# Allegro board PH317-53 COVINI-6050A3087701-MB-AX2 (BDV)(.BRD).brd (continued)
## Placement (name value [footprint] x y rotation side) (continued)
C4146  1uF_6.3V_2  [CSC_100X050X055_2]  124.96 61.7 270 top
C4147  1uF_6.3V_2  [CSC_100X050X055_2]  112.47 62.28 180 top
C4148  10uF_6.3V_3  [CSC_160X080X095_2]  115.41 69.45 0 top
C4149  10uF_6.3V_3  [CSC_160X080X095_2]  115.08 66.09 90 top
C4150  1uF_6.3V_2  [CSC_100X050X055_2]  114.22 63.35 90 top
C4151  1uF_6.3V_2  [CSC_100X050X055_2]  120.27 63.17 90 top
C4152  10uF_6.3V_3  [CSC_160X080X095_2]  121.43 65.1 0 top
C4153  10uF_6.3V_3  [CSC_160X080X095_2]  127 65.51 180 top
C4154  1uF_6.3V_2  [CSC_100X050X055_2]  123.9 72.27 90 top
C4155  1uF_6.3V_2  [CSC_100X050X055_2]  112.16 69.73 270 top
C4156  10uF_6.3V_3  [CSC_160X080X095_2]  123.64 65.76 90 top
C4157  1uF_6.3V_2  [CSC_100X050X055_2]  117.24 70.16 90 top
C4165  0.1uF_16V_2  [CSC_100X050X040_2]  86.51 123.42 90 top
C4167  0.1uF_16V_2  [CSC_100X050X040_2]  82.93 125.35 270 top
C4169  0.022uF_16V_2  [CSC_100X050X040_2]  83.46 126.62 180 top
C4170  0.1uF_16V_2  [CSC_100X050X040_2]  127.12 62.06 0 top
C4171  0.1uF_16V_2  [CSC_100X050X040_2]  79.68 123.55 180 top
C4172  0.022uF_16V_2  [CSC_100X050X040_2]  81.3 122.66 180 top
C4300  220pF_50V_2  [CSC_100X050X040_2]  275.99 75.21 180 top
C4301  CSC0402_DY  [CSC_100X050X040_2]  60.93 58.04 270 bottom
C4303  4.7uF_6.3V_3  [CSC_160X080X080_2]  70.23 57.61 0 bottom
C4304  0.1uF_16V_2  [CSC_100X050X040_2]  70.48 58.75 0 bottom
C4305  220pF_50V_2  [CSC_100X050X040_2]  60.93 56.42 90 bottom
C4306  CSC0402_DY  [CSC_100X050X040_2]  273.94 75.21 0 top
C4307  4.7uF_6.3V_3  [CSC_160X080X080_2]  280.51 70.59 0 bottom
C4308  0.1uF_16V_2  [CSC_100X050X040_2]  280.59 71.99 0 bottom
C4450  0.1uF_16V_2  [CSC_100X050X040_2]  147.85 112.73 270 bottom
C4451  1000PF_50V_2  [CSC_100X050X055_2]  146.22 112.58 180 bottom
C4500  47UF_6.3V_5  [CSC_200X125X145_2]  111.96 147.93 0 bottom
C4501  47UF_6.3V_5  [CSC_200X125X145_2]  118.46 147.96 180 bottom
C4502  47UF_6.3V_5  [CSC_200X125X145_2]  132.25 147.93 0 bottom
C4503  47UF_6.3V_5  [CSC_200X125X145_2]  100.2 156.14 180 top
C4508  10uF_6.3V_2  [CSC_100X050X070_2]  121.26 125.53 180 top
C4509  22uF_6.3V_3  [CSC_160X080X100_2]  102.99 134.01 180 top
C4510  22uF_6.3V_3  [CSC_160X080X100_2]  102.99 135.23 180 top
C4511  22uF_6.3V_3  [CSC_160X080X100_2]  102.99 131.58 180 top
C4512  22uF_6.3V_3  [CSC_160X080X100_2]  102.99 132.79 180 top
C4513  22uF_6.3V_3  [CSC_160X080X100_2]  109.01 133.15 180 top
C4514  22uF_6.3V_3  [CSC_160X080X100_2]  109.01 131.93 180 top
C4515  22uF_6.3V_3  [CSC_160X080X100_2]  113.15 131.98 0 top
C4516  10uF_6.3V_2  [CSC_100X050X070_2]  117.9 136.63 0 top
C4517  10uF_6.3V_2  [CSC_100X050X070_2]  117.9 135.74 0 top
C4518  10uF_6.3V_2  [CSC_100X050X070_2]  103.25 129.95 180 top
C4519  10uF_6.3V_2  [CSC_100X050X070_2]  103.22 128.98 180 top
C4520  10uF_6.3V_2  [CSC_100X050X070_2]  115.67 135.72 0 top
C4521  10uF_6.3V_2  [CSC_100X050X070_2]  115.67 136.61 0 top
C4522  10uF_6.3V_2  [CSC_100X050X070_2]  105.18 128.94 270 top
C4523  10uF_6.3V_2  [CSC_100X050X070_2]  109.29 128.94 270 top
C4524  10uF_6.3V_2  [CSC_100X050X070_2]  112.27 128.94 270 top
C4525  10uF_6.3V_2  [CSC_100X050X070_2]  115.67 134.83 0 top
C4526  10uF_6.3V_2  [CSC_100X050X070_2]  110.18 128.94 270 top
C4527  10uF_6.3V_2  [CSC_100X050X070_2]  111.38 128.94 270 top
C4528  10uF_6.3V_2  [CSC_100X050X070_2]  105.41 136.05 180 top
C4529  10uF_6.3V_2  [CSC_100X050X070_2]  103.48 138.57 270 top
C4530  10uF_6.3V_2  [CSC_100X050X070_2]  119.76 128.94 270 top
C4531  10uF_6.3V_2  [CSC_100X050X070_2]  116.2 128.94 270 top
C4532  10uF_6.3V_2  [CSC_100X050X070_2]  105.41 136.94 180 top
C4533  10uF_6.3V_2  [CSC_100X050X070_2]  106.7 128.93 270 top
C4534  10uF_6.3V_2  [CSC_100X050X070_2]  117.9 134.85 0 top
C4535  10uF_6.3V_2  [CSC_100X050X070_2]  114.58 128.93 270 top
C4536  10uF_6.3V_2  [CSC_100X050X070_2]  117.98 128.94 270 top
C4537  10uF_6.3V_2  [CSC_100X050X070_2]  117.09 128.94 270 top
C4538  22uF_6.3V_3  [CSC_160X080X100_2]  113.15 133.2 0 top
C4539  22uF_6.3V_3  [CSC_160X080X100_2]  109.01 135.59 180 top
C4540  22uF_6.3V_3  [CSC_160X080X100_2]  131.11 138.81 0 top
C4541  22uF_6.3V_3  [CSC_160X080X100_2]  131.11 137.6 0 top
C4549  1uF_6.3V_2  [CSC_100X050X055_2]  114.58 127.23 180 top
C4551  22uF_6.3V_3  [CSC_160X080X100_2]  113.15 135.67 0 top
C4552  1uF_6.3V_2  [CSC_100X050X055_2]  117.96 126.85 90 top
C4554  22uF_6.3V_3  [CSC_160X080X080_2]  100.66 134.01 0 top
C4555  22uF_6.3V_3  [CSC_160X080X100_2]  94.03 130.1 180 top
C4556  1uF_6.3V_2  [CSC_100X050X055_2]  109.42 126.85 90 top
C4557  1uF_6.3V_2  [CSC_100X050X055_2]  110.31 126.85 90 top
C4558  1uF_6.3V_2  [CSC_100X050X055_2]  111.43 126.85 90 top
C4559  1uF_6.3V_2  [CSC_100X050X055_2]  115.97 138.57 270 top
C4560  1uF_6.3V_2  [CSC_100X050X055_2]  117.07 126.85 90 top
C4561  1uF_6.3V_2  [CSC_100X050X055_2]  116.18 126.85 90 top
C4562  1uF_6.3V_2  [CSC_100X050X055_2]  119.81 126.85 90 top
C4563  1uF_6.3V_2  [CSC_100X050X055_2]  111.3 138.57 270 top
C4566  1uF_6.3V_2  [CSC_100X050X055_2]  118.29 138.57 270 top
C4568  1uF_6.3V_2  [CSC_100X050X055_2]  103.38 126.85 90 top
C4580  22uF_6.3V_3  [CSC_160X080X100_2]  100.66 132.79 0 top
C4581  22uF_6.3V_3  [CSC_160X080X100_2]  94.03 133.76 180 top
C4582  22uF_6.3V_3  [CSC_160X080X100_2]  94.03 132.54 180 top
C4583  22uF_6.3V_3  [CSC_160X080X100_2]  94.03 131.32 180 top
C4584  22uF_6.3V_3  [CSC_160X080X100_2]  100.66 130.36 0 top
C4585  22uF_6.3V_3  [CSC_160X080X100_2]  100.66 131.58 0 top
C4588  22uF_6.3V_3  [CSC_160X080X080_2]  100.66 135.23 0 top
C4589  47UF_6.3V_5  [CSC_200X125X145_2]  85.06 150.4 90 bottom
C4594  12pF_50V_2  [CSC_100X050X040_2]  136.7 121.69 270 bottom
C4598  22uF_6.3V_3  [CSC_160X080X100_2]  113.15 134.45 0 top
C4599  22uF_6.3V_3  [CSC_160X080X100_2]  109.01 134.37 180 top
C4600  47UF_6.3V_5  [CSC_200X125X145_2]  86.74 150.4 90 bottom
C4602  47UF_4V_3  [CSC_160X080X100_2]  94.03 134.98 180 top
C4612  47pF_50V_2  [CSC_100X050X040_2]  86.53 140.51 0 top
C4614  1uF_6.3V_2  [CSC_100X050X055_2]  106.6 126.83 90 top
C4626  0.01uF_50V_2  [CSC_100X050X040_2]  71.45 95.41 180 bottom
C4627  1uF_6.3V_2  [CSC_100X050X055_2]  97.84 125.84 180 top
C4628  1uF_6.3V_2  [CSC_100X050X055_2]  90.68 130.05 270 top
C4629  1uF_6.3V_2  [CSC_100X050X055_2]  87.17 130.16 90 top
C4630  1uF_6.3V_2  [CSC_100X050X055_2]  92.53 126.41 180 top
C4631  1uF_6.3V_2  [CSC_100X050X055_2]  92.27 127.3 180 top
C4656  10uF_6.3V_2  [CSC_100X050X070_2]  90.27 132.26 180 top
C4657  10uF_6.3V_2  [CSC_100X050X070_2]  100.53 126.47 0 top
C4658  10uF_6.3V_2  [CSC_100X050X070_2]  97.69 138.89 270 top
C4659  10uF_6.3V_2  [CSC_100X050X070_2]  94.03 129.04 180 top
C4660  1uF_6.3V_2  [CSC_100X050X055_2]  90.75 135.01 180 top
C4661  1uF_6.3V_2  [CSC_100X050X055_2]  98.17 127.18 180 top
C4662  1uF_6.3V_2  [CSC_100X050X055_2]  100.63 129.29 0 top
C4663  1uF_6.3V_2  [CSC_100X050X055_2]  87.45 126.72 180 top
C4667  1uF_6.3V_2  [CSC_100X050X055_2]  105 126.83 90 top
C4668  1uF_6.3V_2  [CSC_100X050X055_2]  93.77 137.29 180 top
C4669  1uF_6.3V_2_DY  [CSC_100X050X055_2]  117.9 132.19 0 top
C4670  1uF_6.3V_2_DY  [CSC_100X050X055_2]  117.9 131.3 0 top
C4679  10uF_6.3V_2_DY  [CSC_100X050X070_2]  107.49 126.83 90 top
C4680  10uF_6.3V_2  [CSC_100X050X070_2]  90.63 133.53 270 top
C4681  10uF_6.3V_2  [CSC_100X050X070_2]  100.84 138.84 270 top
C4682  10uF_6.3V_2  [CSC_100X050X070_2]  88.85 128.61 180 top
C4683  10uF_6.3V_2  [CSC_100X050X070_2]  99.57 138.84 270 top
C4684  10uF_6.3V_2_DY  [CSC_100X050X070_2]  106.47 133.38 0 top
C4685  10uF_6.3V_2_DY  [CSC_100X050X070_2]  117.9 133.07 0 top
C4686  10uF_6.3V_2_DY  [CSC_100X050X070_2]  105.84 138.59 270 top
C4687  10uF_6.3V_2  [CSC_100X050X070_2]  94.89 127.16 180 top
C4688  10uF_6.3V_2  [CSC_100X050X070_2]  94 136.05 180 top
C4689  10uF_6.3V_2_DY  [CSC_100X050X070_2]  120.09 134.62 0 top
C4690  10uF_6.3V_2_DY  [CSC_100X050X070_2]  106.47 131.6 0 top
C4691  10uF_6.3V_2_DY  [CSC_100X050X070_2]  106.47 132.49 0 top
C4692  10uF_6.3V_2_DY  [CSC_100X050X070_2]  109.24 136.66 180 top
C4693  10uF_6.3V_2_DY  [CSC_100X050X070_2]  106.47 134.27 0 top
C4694  10uF_6.3V_2_DY  [CSC_100X050X070_2]  113.1 136.73 0 top
C4695  10uF_6.3V_2_DY  [CSC_100X050X070_2]  113.69 128.93 270 top
C4696  10uF_6.3V_2_DY  [CSC_100X050X070_2]  107.59 128.93 270 top
C4697  1uF_6.3V_2  [CSC_100X050X055_2]  117.4 138.57 270 top
C4698  10uF_6.3V_2_DY  [CSC_100X050X070_2]  114.22 130.92 0 top
C4699  1uF_6.3V_2  [CSC_100X050X055_2]  108.15 138.57 270 top
C4700  10uF_6.3V_2  [CSC_100X050X070_2]  112.8 125.56 90 top
C4701  10uF_6.3V_2  [CSC_100X050X070_2]  113.69 125.56 90 top
C4702  CSC0201_DY  [CSC_060X030X030_2]  64.28 70.95 270 bottom
C4703  47UF_6.3V_5  [CSC_200X125X145_2]  136.65 160.99 90 top
C4704  CSC0201_DY  [CSC_060X030X030_2]  83.74 139.07 270 top
C4705  CSC0201_DY  [CSC_060X030X030_2]  251.13 46.26 0 top
C4706  47UF_6.3V_5  [CSC_200X125X145_2]  138.33 160.99 90 top
C4707  CSC0201_DY  [CSC_060X030X030_2]  247.93 34.47 270 bottom
C4708  22uF_6.3V_3  [CSC_160X080X100_2]  139.8 161.24 90 top
C4709  22uF_6.3V_3  [CSC_160X080X100_2]  141.14 161.24 90 top
C4710  10uF_6.3V_2_DY  [CSC_100X050X070_2]  105.41 135.16 180 top
C4711  10uF_6.3V_2_DY  [CSC_100X050X070_2]  117.9 133.96 0 top
C4712  1uF_6.3V_2  [CSC_100X050X055_2]  244.01 33.07 270 bottom
C4713  1uF_6.3V_2  [CSC_100X050X055_2]  247.44 33.05 0 bottom
C4714  1uF_6.3V_2  [CSC_100X050X055_2]  243.35 31.25 270 bottom
C4715  10uF_6.3V_2_DY  [CSC_100X050X070_2]  115.92 133.94 0 top
C4716  22uF_6.3V_3  [CSC_160X080X100_2]  133.47 141.96 0 top
C4717  10uF_6.3V_3  [CSC_160X080X095_2]  133.47 139.53 0 top
C4718  22uF_6.3V_3  [CSC_160X080X100_2]  133.47 140.74 0 top
C4719  22uF_6.3V_3  [CSC_160X080X100_2]  133.47 143.18 0 top
C4720  47UF_6.3V_5  [CSC_200X125X145_2]  113.94 156.09 0 top
C4721  47UF_6.3V_5_DY  [CSC_200X125X145_2]  116.28 157.74 180 top
C4722  47UF_6.3V_5_DY  [CSC_200X125X145_2]  101.32 157.81 180 top
C4723  47UF_6.3V_5_DY  [CSC_200X125X145_2]  116.89 156.09 180 top
C4726  1uF_6.3V_2  [CSC_100X050X055_2]  90.99 125.94 90 top
C4729  1uF_6.3V_2  [CSC_100X050X055_2]  126.46 136.83 270 top
C4730  1uF_6.3V_2  [CSC_100X050X055_2]  122.6 137.16 270 top
C4731  10uF_6.3V_2  [CSC_100X050X070_2]  122.73 129.49 270 top
C4732  22uF_6.3V_3  [CSC_160X080X100_2]  123.14 109.02 0 top
C4733  10uF_6.3V_2  [CSC_100X050X070_2]  122.65 131.91 90 top
C4744  1uF_6.3V_2  [CSC_100X050X055_2]  102.49 126.85 90 top
C4745  1uF_6.3V_2  [CSC_100X050X055_2]  107.26 138.57 270 top
C4746  1uF_6.3V_2  [CSC_100X050X055_2]  102.59 138.57 270 top
C4753  1uF_6.3V_2  [CSC_100X050X055_2]  104.95 138.59 270 top
C4758  1uF_6.3V_2  [CSC_100X050X055_2]  112.65 138.57 270 top
C4760  1uF_6.3V_2  [CSC_100X050X055_2]  96.72 137.06 0 top
C4761  1uF_6.3V_2  [CSC_100X050X055_2]  99.01 137.06 0 top
C4763  10uF_6.3V_2  [CSC_100X050X070_2]  104.52 124.74 90 top
C4764  22uF_6.3V_3  [CSC_160X080X100_2]  123.14 107.8 0 top
C4765  22uF_6.3V_3  [CSC_160X080X100_2]  86.08 107.34 180 top
C4766  1uF_6.3V_2  [CSC_100X050X055_2]  121.26 138.33 90 top
C4767  18pF_50V_2  [CSC_100X050X040_2]  263.43 38.13 180 bottom
C4768  10uF_6.3V_2  [CSC_100X050X070_2]  98.19 124.95 180 top
C4769  10uF_6.3V_2  [CSC_100X050X070_2]  98.24 123.45 180 top
C4770  10uF_6.3V_2  [CSC_100X050X070_2]  110.26 124.16 270 top
C4771  10uF_6.3V_2  [CSC_100X050X070_2]  85.72 108.41 180 top
C4772  10uF_6.3V_2  [CSC_100X050X070_2]  100.94 125.23 90 top
C4773  10uF_6.3V_2  [CSC_100X050X070_2]  122.88 124.87 0 top
C4774  10uF_6.3V_2  [CSC_100X050X070_2]  85.72 109.3 180 top
C4775  10uF_6.3V_2  [CSC_100X050X070_2]  88.82 125.48 180 top
C4776  22uF_6.3V_3  [CSC_160X080X100_2]  85.72 121.82 180 top
C4778  10uF_6.3V_2  [CSC_100X050X070_2]  119.33 141.58 180 top
C4779  10uF_6.3V_2  [CSC_100X050X070_2]  119.33 140.69 180 top
C4780  10uF_6.3V_2  [CSC_100X050X070_2]  123.77 141.53 270 top
C4781  10uF_6.3V_2  [CSC_100X050X070_2]  119.48 138.45 270 top
C4782  10uF_6.3V_2  [CSC_100X050X070_2]  122.88 141.53 270 top
C4783  10uF_6.3V_2  [CSC_100X050X070_2]  120.57 135.87 270 top
C4785  1uF_6.3V_2  [CSC_100X050X055_2]  87.67 138.64 180 top
C4786  1uF_6.3V_2  [CSC_100X050X055_2]  90.1 125.94 90 top
C4787  10uF_6.3V_2  [CSC_100X050X070_2]  121.59 139.93 0 top
C4788  18pF_50V_2  [CSC_100X050X040_2]  261.8 38.13 0 bottom
C4789  1uF_6.3V_2  [CSC_100X050X055_2]  120.37 138.45 270 top
C4790  1uF_6.3V_2  [CSC_100X050X055_2]  122.68 143.34 0 top
C4791  1uF_6.3V_2  [CSC_100X050X055_2]  142.24 160.91 90 top
C4797  1uF_6.3V_2  [CSC_100X050X055_2]  90.45 128.78 0 top
C4800  1uF_6.3V_2  [CSC_100X050X055_2]  113.54 138.57 270 top
C4802  0.1uF_16V_2_DY  [CSC_100X050X040_2]  111.58 59.08 90 bottom
C4807  1uF_6.3V_2  [CSC_100X050X055_2]  115.09 138.57 270 top
C4808  1uF_6.3V_2  [CSC_100X050X055_2]  110.41 138.57 270 top
C4809  22uF_6.3V_3  [CSC_160X080X100_2]  241.68 71.71 180 bottom
C4810  0.22uF_6.3V_1  [CSC_060X030X030_2]  135.35 130.76 180 bottom
C4811  0.22uF_6.3V_1  [CSC_060X030X030_2]  135.35 130.15 180 bottom
C4812  0.22uF_6.3V_1  [CSC_060X030X030_2]  134.95 132.03 180 bottom
C4813  1uF_6.3V_2  [CSC_100X050X055_2]  258.44 61.6 0 top
C4814  0.1uF_16V_2  [CSC_100X050X040_2]  263.67 39.93 0 bottom
C4815  1uF_6.3V_2  [CSC_100X050X055_2]  242.74 55.1 180 top
C4816  1uF_6.3V_2  [CSC_100X050X055_2]  254.43 35.44 0 bottom
C4817  1uF_6.3V_2  [CSC_100X050X055_2]  254.45 46.28 180 top
C4818  0.22uF_6.3V_1  [CSC_060X030X030_2]  134.74 129.54 180 bottom
C4819  0.22uF_6.3V_1  [CSC_060X030X030_2]  133.04 128.07 180 bottom
C4820  0.22uF_6.3V_1  [CSC_060X030X030_2]  134.74 128.93 180 bottom
C4821  0.22uF_6.3V_1  [CSC_060X030X030_2]  138.66 128.98 180 bottom
C4822  0.22uF_6.3V_1  [CSC_060X030X030_2]  133.04 128.68 180 bottom
C4823  0.22uF_6.3V_1  [CSC_060X030X030_2]  138.66 128.38 180 bottom
C4824  1uF_6.3V_2  [CSC_100X050X055_2]  265.25 37.11 0 bottom
C4825  0.1uF_16V_2  [CSC_100X050X040_2]  265.25 38 0 bottom
C4826  15pF_50V_2  [CSC_100X050X040_2]  244.35 70.29 180 bottom
C4827  1uF_6.3V_2  [CSC_100X050X055_2]  259.38 59.97 90 top
C4828  12pF_50V_2  [CSC_100X050X040_2]  247.55 70.29 0 bottom
C4829  1uF_6.3V_2  [CSC_100X050X055_2]  254.1 52.2 270 top
C4830  1uF_6.3V_2  [CSC_100X050X055_2]  254.86 57.92 0 top
C4831  0.22uF_6.3V_1  [CSC_060X030X030_2]  134.95 131.42 180 bottom
C4832  0.22uF_6.3V_1  [CSC_060X030X030_2]  132.41 126.32 180 bottom
C4833  0.22uF_6.3V_1  [CSC_060X030X030_2]  132.41 126.93 180 bottom
C4834  0.22uF_6.3V_1  [CSC_060X030X030_2]  136.7 132.29 180 bottom
C4835  0.22uF_6.3V_1  [CSC_060X030X030_2]  135.28 136.5 180 bottom
C4836  0.22uF_6.3V_1  [CSC_060X030X030_2]  135.28 137.11 180 bottom
C4837  0.22uF_6.3V_1  [CSC_060X030X030_2]  136.7 135.69 180 bottom
C4838  0.22uF_6.3V_1  [CSC_060X030X030_2]  136.7 136.3 180 bottom
C4839  0.22uF_6.3V_1  [CSC_060X030X030_2]  135.28 134.88 180 bottom
C4840  0.22uF_6.3V_1  [CSC_060X030X030_2]  135.28 135.49 180 bottom
C4841  0.22uF_6.3V_1  [CSC_060X030X030_2]  136.7 134.01 180 bottom
C4842  0.22uF_6.3V_1  [CSC_060X030X030_2]  136.7 134.62 180 bottom
C4843  10uF_6.3V_2  [CSC_100X050X070_2]  246.56 57.39 90 top
C4844  1uF_6.3V_2  [CSC_100X050X055_2]  245.67 57.39 90 top
C4845  22uF_6.3V_3  [CSC_160X080X100_2]  241.68 70.49 180 bottom
C4846  1uF_6.3V_2  [CSC_100X050X055_2]  241.68 68.2 180 bottom
C4847  10uF_6.3V_2  [CSC_100X050X070_2]  238.15 67.34 90 top
C4848  1uF_6.3V_2  [CSC_100X050X055_2]  239.49 66.45 0 top
C4849  1uF_6.3V_2  [CSC_100X050X055_2]  239.49 65.56 0 top
C4850  1uF_6.3V_2  [CSC_100X050X055_2]  240.61 54.74 90 top
C4851  10uF_6.3V_2  [CSC_100X050X070_2]  251.02 53.14 0 top
C4852  22uF_6.3V_3  [CSC_160X080X100_2]  231.09 48.87 270 bottom
C4853  1uF_6.3V_2  [CSC_100X050X055_2]  248.13 49.53 270 top
C4854  1uF_6.3V_2  [CSC_100X050X055_2]  244.34 57.23 90 top
C4855  10uF_6.3V_2  [CSC_100X050X070_2]  241.5 54.74 90 top
C4856  10uF_6.3V_2  [CSC_100X050X070_2]  238.45 37.82 270 bottom
C4857  1uF_6.3V_2  [CSC_100X050X055_2]  233.55 38.15 180 bottom
C4858  1uF_6.3V_2  [CSC_100X050X055_2]  237.26 67.34 90 top
C4859  1uF_6.3V_2  [CSC_100X050X055_2]  265.25 38.89 0 bottom
C4860  1uF_6.3V_2  [CSC_100X050X055_2]  243.96 55.99 180 top
C4861  22uF_6.3V_3  [CSC_160X080X100_2]  229.82 48.87 270 bottom
C4862  1uF_6.3V_2  [CSC_100X050X055_2]  238.78 48.06 270 top
C4863  1uF_6.3V_2  [CSC_100X050X055_2]  237.89 48.06 270 top
C4864  1uF_6.3V_2  [CSC_100X050X055_2]  250.64 50.17 270 top
C4865  1uF_6.3V_2  [CSC_100X050X055_2]  247.67 54.64 90 top
C4866  1uF_6.3V_2  [CSC_100X050X055_2]  247.88 57.39 90 top
C4867  0.1uF_16V_2  [CSC_100X050X040_2]  247.24 48.37 90 top
C4868  0.1uF_16V_2  [CSC_100X050X040_2]  249.42 49.43 90 top
C4869  1uF_6.3V_2  [CSC_100X050X055_2]  254.2 54.69 90 top
C4870  1uF_6.3V_2  [CSC_100X050X055_2]  256.26 60.94 270 top
C4871  0.1uF_16V_2  [CSC_100X050X040_2]  252.22 49.81 180 top
C4872  0.1uF_16V_2  [CSC_100X050X040_2]  252.32 52.2 270 top
C4873  22uF_6.3V_3  [CSC_160X080X100_2]  237.36 37.44 270 bottom
C4874  22uF_6.3V_3  [CSC_160X080X100_2]  236.14 37.44 270 bottom
C4875  1uF_6.3V_2  [CSC_100X050X055_2]  261.57 32.06 270 top
C4876  0.1uF_16V_2  [CSC_100X050X040_2]  260.68 32.06 270 top
C4877  22uF_6.3V_3  [CSC_160X080X100_2]  241.5 69.27 180 bottom
C4878  0.22uF_6.3V_1  [CSC_060X030X030_2]  135.94 125.91 180 bottom
C4879  0.22uF_6.3V_1  [CSC_060X030X030_2]  136.7 132.9 180 bottom
C4880  0.22uF_6.3V_1  [CSC_060X030X030_2]  135.94 126.52 180 bottom
C4881  0.22uF_6.3V_1  [CSC_060X030X030_2]  134.67 125.17 180 bottom
C4882  0.22uF_6.3V_1  [CSC_060X030X030_2]  135.25 133.76 180 bottom
C4883  0.22uF_6.3V_1  [CSC_060X030X030_2]  135.25 133.15 180 bottom
C4884  0.22uF_6.3V_1  [CSC_060X030X030_2]  134.67 124.57 180 bottom
C4885  0.22uF_6.3V_1  [CSC_060X030X030_2]  137.31 124.16 180 bottom
C4886  0.22uF_6.3V_1  [CSC_060X030X030_2]  137.31 124.77 180 bottom
C4887  0.22uF_6.3V_1  [CSC_060X030X030_2]  134.67 122.89 180 bottom
C4888  0.22uF_6.3V_1  [CSC_060X030X030_2]  134.67 123.5 180 bottom
C4890  0.1uF_16V_2_DY  [CSC_100X050X040_2]  240.45 53.03 180 top
C4891  0.1uF_16V_2_DY  [CSC_100X050X040_2]  243.46 57.23 90 top
C4892  0.1uF_16V_2_DY  [CSC_100X050X040_2]  240.08 64.67 0 top
C4954  0.01uF_50V_2  [CSC_100X050X040_2]  234.06 41.35 180 bottom
C4955  0.01uF_50V_2  [CSC_100X050X040_2]  234.06 40.47 180 bottom
C4960  0.1uF_16V_2  [CSC_100X050X040_2]  233.73 45.72 0 bottom
C4961  0.1uF_16V_2  [CSC_100X050X040_2]  233.73 44.83 0 bottom
C6035  1000PF_50V_2  [CSC_100X050X055_2]  13.2 77.65 0 bottom
C6036  0.01uF_50V_2  [CSC_100X050X040_2]  11.3 81.46 90 bottom
C6037  1000PF_50V_2  [CSC_100X050X055_2]  15.11 77.02 270 bottom
C6038  0.01uF_50V_2  [CSC_100X050X040_2]  16 77.02 270 bottom
C7000  0.1uF_16V_2  [CSC_100X050X040_2]  75.69 56.09 180 bottom
C7006  0.1uF_25V_2  [CSC_100X050X040_2]  190.22 29.09 180 bottom
C7010  10uF_6.3V_3  [RANGERS-6010B0044902-001]  232.71 31.5 180 bottom
C7011  1000PF_50V_2  [CSC_100X050X055_2]  222.4 27.97 90 bottom
C7012  220pF_50V_2  [CSC_100X050X040_2]  228.19 36.3 90 bottom
C7013  220pF_50V_2  [CSC_100X050X040_2]  229.56 36.3 90 bottom
C7014  1000PF_50V_2  [CSC_100X050X055_2]  279.85 58.9 270 bottom
C7015  100pF_50V_2_DY  [CSC_100X050X040_2]  66.95 74.17 0 bottom
C7016  1uF_6.3V_2  [CSC_100X050X055_2]  277.49 66.02 90 bottom
C7017  1uF_6.3V_2  [CSC_100X050X055_2]  225.07 32.01 180 bottom
C7018  10uF_6.3V_3  [RANGERS-6010B0044902-001]  227.83 37.9 0 bottom
C7019  1uF_6.3V_2  [CSC_100X050X055_2]  229.79 29.11 270 bottom
C7020  1uF_6.3V_2  [CSC_100X050X055_2]  281.25 62.74 270 bottom
C7023  0.1uF_16V_2  [CSC_100X050X040_2]  192.3 31.3 0 bottom
C7032  0.01uF_50V_2  [CSC_100X050X040_2]  230.15 48.31 270 top
C7033  0.22uF_6.3V_2  [CSC_100X050X040_2]  96.34 57.43 0 bottom
C7034  1000PF_50V_2  [CSC_100X050X055_2]  228.14 48.39 270 top
C7035  1000PF_50V_2  [CSC_100X050X055_2]  230.63 57.48 90 top
C7036  0.022uF_16V_2  [CSC_100X050X040_2]  72.01 98.17 270 bottom
C7037  1uF_6.3V_2  [CSC_100X050X055_2]  226.95 52.73 90 top
C7038  1uF_6.3V_2  [CSC_100X050X055_2]  231.34 52.96 90 top
C7039  CSC0402  [CSC_100X050X040_2]  66.85 94.85 90 bottom
C7041  1uF_6.3V_2  [CSC_100X050X055_2]  70.86 92.1 180 bottom
C7042  1uF_6.3V_2  [CSC_100X050X055_2]  73.05 95.41 0 bottom
C7205  10uF_6.3V_3  [RANGERS-6010B0044902-001]  226.64 55.58 180 top
C7500  0.1uF_16V_2  [CSC_100X050X040_2]  170.76 171.38 90 top
C7501  0.1uF_16V_2  [CSC_100X050X040_2]  201.88 150.8 90 top
C7502  0.1uF_16V_2  [CSC_100X050X040_2]  204.54 111.13 90 top
C7503  0.1uF_16V_2  [CSC_100X050X040_2]  180.16 98.05 90 top
C7504  0.1uF_16V_2  [CSC_100X050X040_2]  198.83 81.82 270 bottom
C7505  0.1uF_16V_2  [CSC_100X050X040_2]  158.11 152.15 180 bottom
C7506  0.1uF_16V_2  [CSC_100X050X040_2]  177.92 177.68 180 bottom
C7507  0.1uF_16V_2  [CSC_100X050X040_2]  211.02 133.07 180 bottom
C7508  0.1uF_16V_2  [CSC_100X050X040_2]  186.99 83.65 0 bottom
C7509  0.1uF_16V_2  [CSC_100X050X040_2]  81.89 140.16 0 bottom
C7510  0.1uF_16V_2  [CSC_100X050X040_2]  79.3 129.09 0 bottom
C7511  0.1uF_16V_2  [CSC_100X050X040_2]  83.77 150.4 270 bottom
C7512  0.1uF_16V_2  [CSC_100X050X040_2]  101.32 159.11 0 top
C7513  0.1uF_16V_2  [CSC_100X050X040_2]  113.97 157.38 180 top
C7545  0.1uF_25V_2  [CSC_100X050X040_2]  50.26 39.5 90 bottom
C7546  0.1uF_16V_2  [CSC_100X050X040_2]  137.33 154.44 180 bottom
C7547  0.1uF_16V_2  [CSC_100X050X040_2]  262.51 26.01 0 top
C7548  0.1uF_25V_2  [CSC_100X050X040_2]  65.4 105.85 90 top
C7549  0.1uF_25V_2  [CSC_100X050X040_2]  124.91 34.04 180 top
C7550  0.1uF_16V_2  [CSC_100X050X040_2]  233.22 52.45 90 bottom
C7551  0.1uF_16V_2  [CSC_100X050X040_2]  296.31 81.26 90 top
C7552  0.1uF_16V_2  [CSC_100X050X040_2]  297.61 47.96 0 top
C7553  0.1uF_16V_2  [CSC_100X050X040_2]  308.86 21.42 180 top
C7554  0.1uF_16V_2  [CSC_100X050X040_2]  309.44 20.35 180 top
C7555  0.1uF_16V_2  [CSC_100X050X040_2]  308.86 21.85 180 bottom
C7558  0.1uF_16V_2  [CSC_100X050X040_2]  301.34 135.06 180 bottom
C7559  0.1uF_16V_2  [CSC_100X050X040_2]  301.34 134.17 180 bottom
C7560  0.1uF_25V_2  [CSC_100X050X040_2]  237.94 31.04 0 top
C7561  0.1uF_25V_2  [CSC_100X050X040_2]  44.98 78.79 180 top
C7562  0.1uF_25V_2  [CSC_100X050X040_2]  76.27 156.34 90 top
C7563  0.1uF_25V_2  [CSC_100X050X040_2]  73.76 59.46 0 top
C7564  0.1uF_25V_2  [CSC_100X050X040_2]  194.71 81.31 180 bottom
C7565  0.1uF_25V_2  [CSC_100X050X040_2]  140 47.1 90 top
C7566  0.1uF_25V_2  [CSC_100X050X040_2]  208.18 75.52 0 top
C7567  0.1uF_25V_2  [CSC_100X050X040_2]  168.2 76.51 180 top
C7568  0.1uF_25V_2  [CSC_100X050X040_2]  157.71 154.74 0 bottom
C7569  0.1uF_16V_2  [CSC_100X050X040_2]  301.98 136 180 bottom
C7570  0.1uF_25V_2  [CSC_100X050X040_2]  206.19 29.21 180 top
C7571  0.1uF_25V_2  [CSC_100X050X040_2]  80.21 110.16 270 bottom
C7572  0.1uF_25V_2  [CSC_100X050X040_2]  82.52 71.58 270 bottom
C7573  0.1uF_16V_2  [CSC_100X050X040_2]  300 32.72 270 top
C7574  0.1uF_16V_2  [CSC_100X050X040_2]  301.98 136.88 180 bottom
C7575  0.1uF_16V_2  [CSC_100X050X040_2]  302.13 114.94 180 top
C7576  0.1uF_16V_2  [CSC_100X050X040_2]  302.1 116.51 180 top
C7577  0.1uF_16V_2  [CSC_100X050X040_2]  302.13 114.99 180 bottom
C7578  0.1uF_16V_2  [CSC_100X050X040_2]  302.1 116.34 180 bottom
C7579  0.1uF_16V_2  [CSC_100X050X040_2]  306.73 60.71 0 top
C7580  0.1uF_16V_2  [CSC_100X050X040_2]  306.73 59.41 0 top
C7581  0.1uF_16V_2  [CSC_100X050X040_2]  306.73 59.67 0 bottom
C7582  0.1uF_16V_2  [CSC_100X050X040_2]  306.73 60.66 0 bottom
C7583  0.1uF_16V_2  [CSC_100X050X040_2]  309.44 20.58 180 bottom
C7600  100pF_50V_2  [CSC_100X050X040_2]  24.46 32.97 0 top
C7601  100pF_50V_2  [CSC_100X050X040_2]  28.11 33.94 180 top
C7602  100pF_50V_2  [CSC_100X050X040_2]  26.64 32.01 180 top
C7689  0.1uF_25V_2_DY  [CSC_100X050X040_2]  16.74 32.11 180 top
C7699  0.1uF_25V_2  [CSC_100X050X040_2]  16.74 33 180 top
C50020  0.1uF_16V_2  [CSC_100X050X040_2]  145.84 41.86 0 bottom
C50030  1uF_6.3V_1  [CSC_060X030X039_2]  157.74 134.61 270 top
C50031  1uF_6.3V_1  [CSC_060X030X039_2]  158.34 134.61 270 top
C50032  1uF_6.3V_1  [CSC_060X030X039_2]  156.84 138.54 180 top
C50033  1uF_6.3V_1  [CSC_060X030X039_2]  159.51 139.14 0 top
C50034  1uF_6.3V_1  [CSC_060X030X039_2]  159.53 136.12 0 top
C50035  1uF_6.3V_1  [CSC_060X030X039_2]  156.74 137.27 180 top
C50036  1uF_6.3V_1  [CSC_060X030X039_2]  156.77 136.05 180 top
C50037  1uF_6.3V_1  [CSC_060X030X039_2]  156.77 136.66 180 top
C50038  4.7uF_6.3V_2  [CSC_100X050X065_2]  148.97 166.86 180 top
C50039  4.7uF_6.3V_2  [CSC_100X050X065_2]  156.82 140.08 90 top
C50040  10uF_10V_5  [CSC_200X125X140_2]  151.81 167.96 0 top
C50041  10uF_10V_5  [CSC_200X125X140_2]  151.81 169.62 0 top
C50042  22uF_4V_3  [CSC_160X080X100_2]  151.81 166.37 0 top
C50050  1uF_6.3V_1  [CSC_060X030X039_2]  158.98 140.01 90 top
C50051  1uF_6.3V_1  [CSC_060X030X039_2]  159.51 136.73 0 top
C50052  1uF_6.3V_1  [CSC_060X030X039_2]  159.51 137.33 0 top
C50053  1uF_6.3V_1  [CSC_060X030X039_2]  159.51 137.93 0 top
C50054  1uF_6.3V_1  [CSC_060X030X039_2]  159.51 138.53 0 top
C50055  1uF_6.3V_1  [CSC_060X030X039_2]  156.71 135.13 180 top
C50056  1uF_6.3V_1  [CSC_060X030X039_2]  156.71 134.52 180 top
C50057  1uF_6.3V_1  [CSC_060X030X039_2]  156.74 137.93 180 top
C50058  4.7uF_6.3V_2  [CSC_100X050X065_2]  148.99 165.94 180 top
C50059  10uF_10V_5  [CSC_200X125X140_2]  148.71 169.62 180 top
C50060  22uF_4V_3  [CSC_160X080X100_2]  148.71 167.95 180 top
C50070  1uF_6.3V_1  [CSC_060X030X039_2]  156.83 130.98 180 top
C50071  1uF_6.3V_1  [CSC_060X030X039_2]  159.52 132.07 0 top
C50072  1uF_6.3V_1  [CSC_060X030X039_2]  158.12 130.18 180 top
C50073  1uF_6.3V_1  [CSC_060X030X039_2]  158.12 129.58 180 top
C50074  1uF_6.3V_1  [CSC_060X030X039_2]  156.83 131.58 180 top
C50075  4.7uF_6.3V_2  [CSC_100X050X065_2]  157.04 133.38 180 top
C50076  4.7uF_6.3V_2  [CSC_100X050X065_2]  143.25 139.68 270 bottom
C50077  10uF_10V_5  [CSC_200X125X140_2]  142.63 142.33 90 bottom
C50078  10uF_10V_5  [CSC_200X125X140_2]  141.74 139.06 270 bottom
C50079  22uF_4V_3  [CSC_160X080X100_2]  140.09 139.06 270 bottom
C50080  1uF_6.3V_1  [CSC_060X030X039_2]  156.77 130.23 180 top
C50081  1uF_6.3V_1  [CSC_060X030X039_2]  159.6 129.66 0 top
C50082  1uF_6.3V_1  [CSC_060X030X039_2]  159.6 130.26 0 top
C50083  1uF_6.3V_1  [CSC_060X030X039_2]  159.6 130.86 0 top
C50084  1uF_6.3V_1  [CSC_060X030X039_2]  159.52 131.46 0 top
C50085  4.7uF_6.3V_2  [CSC_100X050X065_2]  145.18 142.35 90 bottom
C50086  10uF_10V_5  [CSC_200X125X140_2]  138.43 139.06 270 bottom
C50087  22uF_4V_3  [CSC_160X080X100_2]  144.07 142.48 90 bottom
C50090  1uF_6.3V_1  [CSC_060X030X039_2]  159.5 132.75 0 top
C50091  1uF_6.3V_1  [CSC_060X030X039_2]  159.51 133.73 0 top
C50092  4.7uF_6.3V_2  [CSC_100X050X065_2]  159.61 134.85 90 top
C50100  1uF_6.3V_1  [CSC_060X030X039_2]  164.26 140.41 270 top
C50101  4.7uF_6.3V_2  [CSC_100X050X065_2]  170.1 140.82 270 top
C50102  4.7uF_6.3V_2  [CSC_100X050X065_2]  179.38 139.2 180 top
C50103  22uF_4V_3  [CSC_160X080X100_2]  188.85 158.55 180 top
C50110  1uF_6.3V_1  [CSC_060X030X039_2]  169.26 141.04 270 top
C50111  1uF_6.3V_1  [CSC_060X030X039_2]  179.15 132.83 180 top
C50200  1uF_6.3V_1  [CSC_060X030X039_2]  179.19 138.43 180 top
C50300  1uF_6.3V_1  [CSC_060X030X039_2]  179.04 123.66 180 top
C50400  1uF_6.3V_1  [CSC_060X030X039_2]  175.03 120.82 90 top
C50510  10uF_4V_3  [CSC_160X080X090_2]  181.68 168.94 180 top
C50511  10uF_4V_3  [CSC_160X080X090_2]  177.2 160.68 270 top
C50512  10uF_4V_3  [CSC_160X080X090_2]  173.21 164.26 270 top
C50513  10uF_4V_3  [CSC_160X080X090_2]  186.99 173.74 90 top
C50514  10uF_4V_3  [CSC_160X080X090_2]  173.07 171.83 90 top
C50515  10uF_4V_3  [CSC_160X080X090_2]  173.07 174.76 90 top
C50516  22uF_4V_3  [CSC_160X080X100_2]  185.24 177.78 180 bottom
C50517  22uF_4V_3  [CSC_160X080X100_2]  182.29 177.78 0 bottom
C50518  22uF_4V_3  [CSC_160X080X100_2]  179.9 177.78 180 bottom
C50519  22uF_4V_3  [CSC_160X080X100_2]  175.89 177.78 0 bottom
C50520  22uF_4V_3  [CSC_160X080X100_2]  189.43 175.31 270 bottom
C50521  22uF_4V_3  [CSC_160X080X100_2]  177.16 175.77 270 top
C50522  1uF_6.3V_1  [CSC_060X030X039_2]  174.27 170.72 90 top
C50523  1uF_6.3V_1  [CSC_060X030X039_2]  185.98 161.9 90 top
C50524  1uF_6.3V_1  [CSC_060X030X039_2]  174.29 174.58 270 top
C50525  1uF_6.3V_1  [CSC_060X030X039_2]  178.23 170.49 270 top
C50526  1uF_6.3V_1  [CSC_060X030X039_2]  176.4 167.21 0 top
C50527  1uF_6.3V_1  [CSC_060X030X039_2]  174.29 163.33 90 top
C50528  1uF_6.3V_1  [CSC_060X030X039_2]  175.23 160.89 0 top
C50529  1uF_6.3V_1  [CSC_060X030X039_2]  174.29 173.08 270 top
C50530  1uF_6.3V_1  [CSC_060X030X039_2]  179.22 173.82 270 top
C50531  1uF_6.3V_1  [CSC_060X030X039_2]  174.32 164.87 90 top
C50532  1uF_6.3V_1  [CSC_060X030X039_2]  174.29 161.8 90 top
C50533  1uF_6.3V_1  [CSC_060X030X039_2]  182.37 170.49 0 top
C50534  1uF_6.3V_1  [CSC_060X030X039_2]  188.49 174.7 270 bottom
C50535  1uF_6.3V_1  [CSC_060X030X039_2]  172.79 171.58 270 bottom
C50536  1uF_6.3V_1  [CSC_060X030X039_2]  185.95 164.8 90 top
C50537  1uF_6.3V_1  [CSC_060X030X039_2]  179.37 163.22 90 top
C50538  1uF_6.3V_1  [CSC_060X030X039_2]  179.38 164.84 90 top
C50539  1uF_6.3V_1  [CSC_060X030X039_2]  185.92 170.87 270 top
C50540  1uF_6.3V_1  [CSC_060X030X039_2]  181.02 174.5 90 top
C50541  1uF_6.3V_1  [CSC_060X030X039_2]  185.95 172.37 90 top
C50542  1uF_6.3V_1  [CSC_060X030X039_2]  181.91 171.96 90 top
C50543  1uF_6.3V_1  [CSC_060X030X039_2]  188.49 173.46 270 bottom
C50544  1uF_6.3V_1  [CSC_060X030X039_2]  174.27 171.83 270 top
C50545  1uF_6.3V_1  [CSC_060X030X039_2]  178.69 171.91 180 top
C50546  4.7uF_6.3V_2  [CSC_100X050X065_2]  182.34 176.28 0 top
C50547  1uF_6.3V_1  [CSC_060X030X039_2]  178.38 161.57 180 top
C50548  1uF_6.3V_1  [CSC_060X030X039_2]  182.04 160.89 0 top
C50549  1uF_6.3V_1  [CSC_060X030X039_2]  178.33 175.52 180 top
C50550  1uF_6.3V_1  [CSC_060X030X039_2]  182.27 175.52 0 top
C50551  1uF_6.3V_1  [CSC_060X030X039_2]  184.3 166.91 180 top
C50552  1uF_6.3V_1  [CSC_060X030X039_2]  181.1 162.56 90 top
C50553  1uF_6.3V_1  [CSC_060X030X039_2]  185.95 163.35 90 top
C50554  1uF_6.3V_1  [CSC_060X030X039_2]  182.39 165.94 0 top
C50555  1uF_6.3V_1  [CSC_060X030X039_2]  185.04 175.52 180 top
C50556  1uF_6.3V_1  [CSC_060X030X039_2]  185.44 168.96 270 top
C50557  1uF_6.3V_1  [CSC_060X030X039_2]  185.98 173.84 90 top
C50558  1uF_6.3V_1  [CSC_060X030X039_2]  185.87 166.6 270 top
C50559  1uF_6.3V_1  [CSC_060X030X039_2]  172.84 174.91 270 bottom
C50560  1uF_6.3V_1  [CSC_060X030X039_2]  174.32 166.37 270 top
C50561  1uF_6.3V_1  [CSC_060X030X039_2]  175.31 175.54 0 top
C50562  1uF_6.3V_1  [CSC_060X030X039_2]  172.82 173.16 270 bottom
C50610  10uF_4V_3  [CSC_160X080X090_2]  156.15 169.47 0 top
C50611  10uF_4V_3  [CSC_160X080X090_2]  164.21 167.82 180 top
C50612  10uF_4V_3  [CSC_160X080X090_2]  157.22 164.65 90 top
C50613  10uF_4V_3  [CSC_160X080X090_2]  156.74 177.78 0 bottom
C50614  10uF_4V_3  [CSC_160X080X090_2]  170.74 174.81 270 top
C50615  10uF_4V_3  [CSC_160X080X090_2]  169.49 162.18 0 top
C50616  22uF_4V_3  [CSC_160X080X100_2]  162.84 177.78 180 bottom
C50617  22uF_4V_3  [CSC_160X080X100_2]  169.44 177.78 180 bottom
C50618  22uF_4V_3  [CSC_160X080X100_2]  161.13 175.75 270 top
C50619  22uF_4V_3  [CSC_160X080X100_2]  172.49 177.78 180 bottom
C50620  22uF_4V_3  [CSC_160X080X100_2]  166.52 177.78 0 bottom
C50621  22uF_4V_3  [CSC_160X080X100_2]  159.15 177.78 0 bottom
C50622  1uF_6.3V_1  [CSC_060X030X039_2]  155.83 174.7 270 bottom
C50623  1uF_6.3V_1  [CSC_060X030X039_2]  155.83 171.63 270 bottom
C50624  1uF_6.3V_1  [CSC_060X030X039_2]  171.57 173.16 270 bottom
C50625  1uF_6.3V_1  [CSC_060X030X039_2]  170.18 173.03 270 top
C50626  1uF_6.3V_1  [CSC_060X030X039_2]  170.1 163.35 90 top
C50627  1uF_6.3V_1  [CSC_060X030X039_2]  157.98 166.75 180 top
C50628  1uF_6.3V_1  [CSC_060X030X039_2]  158.29 174.58 270 top
C50629  1uF_6.3V_1  [CSC_060X030X039_2]  169.41 166.68 0 top
C50630  1uF_6.3V_1  [CSC_060X030X039_2]  155.83 173.18 270 bottom
C50631  1uF_6.3V_1  [CSC_060X030X039_2]  171.57 171.63 270 bottom
C50632  1uF_6.3V_1  [CSC_060X030X039_2]  171.57 174.93 270 bottom
C50633  1uF_6.3V_1  [CSC_060X030X039_2]  161.64 169.7 270 top
C50634  1uF_6.3V_1  [CSC_060X030X039_2]  168.14 167.57 180 top
C50635  1uF_6.3V_1  [CSC_060X030X039_2]  158.26 173.03 270 top
C50636  1uF_6.3V_1  [CSC_060X030X039_2]  161.69 165.97 270 top
C50637  1uF_6.3V_1  [CSC_060X030X039_2]  165.07 164.98 90 top
C50638  1uF_6.3V_1  [CSC_060X030X039_2]  165.07 171.15 90 top
C50639  1uF_6.3V_1  [CSC_060X030X039_2]  165.1 162.72 90 top
C50640  1uF_6.3V_1  [CSC_060X030X039_2]  158.31 165.59 90 top
C50641  1uF_6.3V_1  [CSC_060X030X039_2]  163.27 173.82 270 top
C50642  1uF_6.3V_1  [CSC_060X030X039_2]  170 171.63 270 top
C50643  1uF_6.3V_1  [CSC_060X030X039_2]  168.48 160.83 180 top
C50644  1uF_6.3V_1  [CSC_060X030X039_2]  158.35 164.3 270 top
C50645  1uF_6.3V_1  [CSC_060X030X039_2]  162.43 171.83 90 top
C50646  4.7uF_6.3V_2  [CSC_100X050X065_2]  165.93 176.25 0 top
C50647  1uF_6.3V_1  [CSC_060X030X039_2]  165.1 161.6 90 top
C50648  1uF_6.3V_1  [CSC_060X030X039_2]  162.3 175.54 180 top
C50649  1uF_6.3V_1  [CSC_060X030X039_2]  165.91 175.47 0 top
C50650  1uF_6.3V_1  [CSC_060X030X039_2]  162.5 162.2 90 top
C50651  1uF_6.3V_1  [CSC_060X030X039_2]  162.51 163.33 90 top
C50652  1uF_6.3V_1  [CSC_060X030X039_2]  166.37 170.49 0 top
C50653  1uF_6.3V_1  [CSC_060X030X039_2]  169.19 165.23 90 top
C50654  1uF_6.3V_1  [CSC_060X030X039_2]  158.21 171.61 270 top
C50655  1uF_6.3V_1  [CSC_060X030X039_2]  162.68 165.21 0 top
C50656  1uF_6.3V_1  [CSC_060X030X039_2]  165.91 172.8 270 top
C50657  1uF_6.3V_1  [CSC_060X030X039_2]  158.16 170.03 90 top
C50658  1uF_6.3V_1  [CSC_060X030X039_2]  161.97 166.85 180 top
C50659  1uF_6.3V_1  [CSC_060X030X039_2]  166.37 166.02 0 top
C50660  1uF_6.3V_1  [CSC_060X030X039_2]  159.29 175.59 0 top
C50661  1uF_6.3V_1  [CSC_060X030X039_2]  169.03 175.7 180 top
C50662  1uF_6.3V_1  [CSC_060X030X039_2]  158.36 163.19 90 top
C50710  10uF_4V_3  [CSC_160X080X090_2]  210.54 136.66 180 top
C50711  10uF_4V_3  [CSC_160X080X090_2]  206.39 141.93 90 top
C50712  10uF_4V_3  [CSC_160X080X090_2]  199.74 146.23 180 top
C50713  10uF_4V_3  [CSC_160X080X090_2]  212.98 136.66 180 top
C50714  10uF_4V_3  [CSC_160X080X090_2]  208.25 135.84 90 top
C50715  10uF_4V_3  [CSC_160X080X090_2]  213.03 150.22 0 top
C50716  22uF_4V_3  [CSC_160X080X100_2]  213.87 134.16 180 bottom
C50717  22uF_4V_3  [CSC_160X080X100_2]  199.31 148.31 270 top
C50718  22uF_4V_3  [CSC_160X080X100_2]  200.25 150.63 0 top
C50719  22uF_4V_3  [CSC_160X080X100_2]  204.16 150.41 180 top
C50720  22uF_4V_3  [CSC_160X080X100_2]  207.95 134.14 180 bottom
C50721  22uF_4V_3  [CSC_160X080X100_2]  210.89 134.14 0 bottom
C50722  1uF_6.3V_1  [CSC_060X030X039_2]  213.59 149.27 180 top
C50723  1uF_6.3V_1  [CSC_060X030X039_2]  203.76 144.15 180 top
C50724  1uF_6.3V_1  [CSC_060X030X039_2]  210.97 141.65 0 top
C50725  1uF_6.3V_1  [CSC_060X030X039_2]  209.88 137.64 180 top
C50726  1uF_6.3V_1  [CSC_060X030X039_2]  210.69 144.28 180 top
C50727  1uF_6.3V_1  [CSC_060X030X039_2]  206.04 144.89 90 top
C50728  1uF_6.3V_1  [CSC_060X030X039_2]  212.16 150.74 180 bottom
C50729  1uF_6.3V_1  [CSC_060X030X039_2]  203.88 149.25 0 top
C50730  1uF_6.3V_1  [CSC_060X030X039_2]  203.91 137.62 0 top
C50731  1uF_6.3V_1  [CSC_060X030X039_2]  202.33 149.27 0 top
C50732  1uF_6.3V_1  [CSC_060X030X039_2]  212.85 137.59 0 top
C50733  1uF_6.3V_1  [CSC_060X030X039_2]  205 145.6 90 top
C50734  1uF_6.3V_1  [CSC_060X030X039_2]  209.5 141.19 270 top
C50735  1uF_6.3V_1  [CSC_060X030X039_2]  205.53 138.05 270 top
C50736  1uF_6.3V_1  [CSC_060X030X039_2]  213.71 135.1 180 bottom
C50737  1uF_6.3V_1  [CSC_060X030X039_2]  209.23 149.28 0 top
C50738  1uF_6.3V_1  [CSC_060X030X039_2]  203.28 142.43 180 top
C50739  1uF_6.3V_1  [CSC_060X030X039_2]  205.53 139.17 90 top
C50740  1uF_6.3V_1  [CSC_060X030X039_2]  212.87 142.45 180 top
C50741  1uF_6.3V_1  [CSC_060X030X039_2]  210.59 150.77 180 bottom
C50742  1uF_6.3V_1  [CSC_060X030X039_2]  212.09 149.27 180 top
C50743  1uF_6.3V_1  [CSC_060X030X039_2]  202.1 144.1 0 top
C50744  1uF_6.3V_1  [CSC_060X030X039_2]  210.56 142.78 0 top
C50745  1uF_6.3V_1  [CSC_060X030X039_2]  211.37 135.09 0 bottom
C50746  4.7uF_6.3V_2  [CSC_100X050X065_2]  215.29 145.77 90 top
C50747  1uF_6.3V_1  [CSC_060X030X039_2]  214.52 145.6 90 top
C50748  1uF_6.3V_1  [CSC_060X030X039_2]  214.5 141.5 270 top
C50749  1uF_6.3V_1  [CSC_060X030X039_2]  200.58 145.04 90 top
C50750  1uF_6.3V_1  [CSC_060X030X039_2]  199.9 141.52 270 top
C50751  1uF_6.3V_1  [CSC_060X030X039_2]  210.59 149.25 180 top
C50752  1uF_6.3V_1  [CSC_060X030X039_2]  209.5 145.33 180 top
C50753  1uF_6.3V_1  [CSC_060X030X039_2]  211.38 137.61 0 top
C50754  1uF_6.3V_1  [CSC_060X030X039_2]  214.46 138.54 90 top
C50755  1uF_6.3V_1  [CSC_060X030X039_2]  213.92 150.72 180 bottom
C50756  1uF_6.3V_1  [CSC_060X030X039_2]  205.38 149.25 180 top
C50757  1uF_6.3V_1  [CSC_060X030X039_2]  212.98 144.28 180 top
C50758  1uF_6.3V_1  [CSC_060X030X039_2]  200.81 149.27 0 top
C50759  1uF_6.3V_1  [CSC_060X030X039_2]  204.95 141.23 270 top
C50760  1uF_6.3V_1  [CSC_060X030X039_2]  201.57 142.46 0 top
C50761  1uF_6.3V_1  [CSC_060X030X039_2]  208.43 137.56 180 top
C50762  1uF_6.3V_1  [CSC_060X030X039_2]  214.55 148.25 270 top
C50810  10uF_4V_3  [CSC_160X080X090_2]  213.79 152.21 180 top
C50811  10uF_4V_3  [CSC_160X080X090_2]  199.62 163 90 top
C50812  10uF_4V_3  [CSC_160X080X090_2]  199.69 154.94 180 top
C50813  10uF_4V_3  [CSC_160X080X090_2]  206.8 158.63 90 top
C50814  10uF_4V_3  [CSC_160X080X090_2]  211.48 167.95 180 bottom
C50815  10uF_4V_3  [CSC_160X080X090_2]  201.83 165.53 0 top
C50816  22uF_4V_3  [CSC_160X080X100_2]  199.41 157.03 270 top
C50817  22uF_4V_3  [CSC_160X080X100_2]  212.01 171.28 90 bottom
C50818  22uF_4V_3  [CSC_160X080X100_2]  208.96 167.95 180 bottom
C50819  22uF_4V_3  [CSC_160X080X100_2]  213.23 165.71 0 top
C50820  22uF_4V_3  [CSC_160X080X100_2]  215.36 154.44 90 top
C50821  22uF_4V_3  [CSC_160X080X100_2]  214.27 167.95 180 bottom
C50822  1uF_6.3V_1  [CSC_060X030X039_2]  212.14 151.38 180 bottom
C50823  1uF_6.3V_1  [CSC_060X030X039_2]  213.66 167.03 180 bottom
C50824  1uF_6.3V_1  [CSC_060X030X039_2]  213.59 164.57 180 top
C50825  1uF_6.3V_1  [CSC_060X030X039_2]  205.56 153.47 270 top
C50826  1uF_6.3V_1  [CSC_060X030X039_2]  214.58 163.66 270 top
C50827  1uF_6.3V_1  [CSC_060X030X039_2]  212.11 164.57 180 top
C50828  1uF_6.3V_1  [CSC_060X030X039_2]  203.3 152.81 180 top
C50829  1uF_6.3V_1  [CSC_060X030X039_2]  208.76 161.22 180 top
C50830  1uF_6.3V_1  [CSC_060X030X039_2]  200.66 153.39 90 top
C50831  1uF_6.3V_1  [CSC_060X030X039_2]  210.92 160.43 0 top
C50832  1uF_6.3V_1  [CSC_060X030X039_2]  213.92 151.38 180 bottom
C50833  1uF_6.3V_1  [CSC_060X030X039_2]  212.01 152.78 180 top
C50834  1uF_6.3V_1  [CSC_060X030X039_2]  209.47 156.59 270 top
C50835  1uF_6.3V_1  [CSC_060X030X039_2]  202.18 152.81 0 top
C50836  1uF_6.3V_1  [CSC_060X030X039_2]  209.47 164.47 0 top
C50837  1uF_6.3V_1  [CSC_060X030X039_2]  200.83 164.52 0 top
C50838  1uF_6.3V_1  [CSC_060X030X039_2]  210.62 167.03 180 bottom
C50839  1uF_6.3V_1  [CSC_060X030X039_2]  210.62 151.38 180 bottom
C50840  1uF_6.3V_1  [CSC_060X030X039_2]  206.55 154.81 90 top
C50841  1uF_6.3V_1  [CSC_060X030X039_2]  212.14 167.03 180 bottom
C50842  1uF_6.3V_1  [CSC_060X030X039_2]  207.26 163.76 0 top
C50843  1uF_6.3V_1  [CSC_060X030X039_2]  212.24 157 180 top
C50844  1uF_6.3V_1  [CSC_060X030X039_2]  212.8 159.68 180 top
C50845  1uF_6.3V_1  [CSC_060X030X039_2]  209.67 160.02 90 top
C50846  4.7uF_6.3V_2  [CSC_100X050X065_2]  214.97 157.02 270 top
C50847  1uF_6.3V_1  [CSC_060X030X039_2]  199.92 161.22 90 top
C50848  1uF_6.3V_1  [CSC_060X030X039_2]  201.6 157.96 0 top
C50849  1uF_6.3V_1  [CSC_060X030X039_2]  213.74 156.76 270 top
C50850  1uF_6.3V_1  [CSC_060X030X039_2]  214.53 160.65 90 top
C50851  1uF_6.3V_1  [CSC_060X030X039_2]  210.16 157.89 0 top
C50852  1uF_6.3V_1  [CSC_060X030X039_2]  205 156.59 270 top
C50853  1uF_6.3V_1  [CSC_060X030X039_2]  203.96 157.88 0 top
C50854  1uF_6.3V_1  [CSC_060X030X039_2]  202.38 164.54 0 top
C50855  1uF_6.3V_1  [CSC_060X030X039_2]  203.86 164.54 0 top
C50856  1uF_6.3V_1  [CSC_060X030X039_2]  210.62 152.78 180 top
C50857  1uF_6.3V_1  [CSC_060X030X039_2]  205.74 160.91 90 top
C50858  1uF_6.3V_1  [CSC_060X030X039_2]  210.61 164.57 180 top
C50859  1uF_6.3V_1  [CSC_060X030X039_2]  201.95 160.33 0 top
C50860  1uF_6.3V_1  [CSC_060X030X039_2]  205.36 164.54 180 top
C50861  1uF_6.3V_1  [CSC_060X030X039_2]  203.58 160.68 270 top
C50862  1uF_6.3V_1  [CSC_060X030X039_2]  204.42 152.81 0 top
C50910  10uF_4V_3  [CSC_160X080X090_2]  210.36 111.66 0 top
C50911  10uF_4V_3  [CSC_160X080X090_2]  206.13 103.31 90 top
C50912  10uF_4V_3  [CSC_160X080X090_2]  199.34 107.77 180 top
C50913  10uF_4V_3  [CSC_160X080X090_2]  211.08 97.83 180 top
C50914  10uF_4V_3  [CSC_160X080X090_2]  213.2 111.66 0 top
C50915  10uF_4V_3  [CSC_160X080X090_2]  202.92 111.76 180 top
C50916  22uF_4V_3  [CSC_160X080X100_2]  217.44 96.58 0 bottom
C50917  22uF_4V_3  [CSC_160X080X100_2]  216.79 102.68 270 bottom
C50918  22uF_4V_3  [CSC_160X080X100_2]  217.45 100.44 0 bottom
C50919  22uF_4V_3  [CSC_160X080X100_2]  216.79 105.12 90 bottom
C50920  22uF_4V_3  [CSC_160X080X100_2]  211.53 96.27 180 bottom
C50921  22uF_4V_3  [CSC_160X080X100_2]  217.45 97.82 0 bottom
C50922  1uF_6.3V_1  [CSC_060X030X039_2]  201.9 105.49 0 top
C50923  1uF_6.3V_1  [CSC_060X030X039_2]  205.57 100.67 90 top
C50924  1uF_6.3V_1  [CSC_060X030X039_2]  210.44 105.62 180 top
C50925  1uF_6.3V_1  [CSC_060X030X039_2]  212.75 105.62 180 top
C50926  1uF_6.3V_1  [CSC_060X030X039_2]  210.59 103.05 0 top
C50927  1uF_6.3V_1  [CSC_060X030X039_2]  209.15 106.74 180 top
C50928  1uF_6.3V_1  [CSC_060X030X039_2]  200.56 98.99 0 top
C50929  1uF_6.3V_1  [CSC_060X030X039_2]  203.27 106.28 270 top
C50930  1uF_6.3V_1  [CSC_060X030X039_2]  201.22 103.87 0 top
C50931  1uF_6.3V_1  [CSC_060X030X039_2]  210.24 112.18 180 bottom
C50932  1uF_6.3V_1  [CSC_060X030X039_2]  202.01 99.02 0 top
C50933  1uF_6.3V_1  [CSC_060X030X039_2]  199.55 109.74 270 top
C50934  1uF_6.3V_1  [CSC_060X030X039_2]  204.52 106.94 90 top
C50935  1uF_6.3V_1  [CSC_060X030X039_2]  210.24 110.65 180 top
C50936  1uF_6.3V_1  [CSC_060X030X039_2]  207.67 100.93 90 top
C50937  1uF_6.3V_1  [CSC_060X030X039_2]  210.33 98.99 180 top
C50938  1uF_6.3V_1  [CSC_060X030X039_2]  210.26 112.79 180 bottom
C50939  1uF_6.3V_1  [CSC_060X030X039_2]  209.15 102.6 270 top
C50940  1uF_6.3V_1  [CSC_060X030X039_2]  204.6 102.58 270 top
C50941  1uF_6.3V_1  [CSC_060X030X039_2]  213.24 110.68 180 top
C50942  1uF_6.3V_1  [CSC_060X030X039_2]  214.25 109.76 270 top
C50943  1uF_6.3V_1  [CSC_060X030X039_2]  205.31 99.8 180 top
C50944  1uF_6.3V_1  [CSC_060X030X039_2]  200.46 110.68 0 top
C50945  1uF_6.3V_1  [CSC_060X030X039_2]  208.99 110.67 0 top
C50946  4.7uF_6.3V_2  [CSC_100X050X065_2]  214.96 103.08 270 top
C50947  1uF_6.3V_1  [CSC_060X030X039_2]  199.55 102.93 270 top
C50948  1uF_6.3V_1  [CSC_060X030X039_2]  200.25 106.58 90 top
C50949  1uF_6.3V_1  [CSC_060X030X039_2]  214.42 106.71 90 top
C50950  1uF_6.3V_1  [CSC_060X030X039_2]  214.17 103.13 270 top
C50951  1uF_6.3V_1  [CSC_060X030X039_2]  211.74 110.68 180 top
C50952  1uF_6.3V_1  [CSC_060X030X039_2]  214.18 99.93 90 top
C50953  1uF_6.3V_1  [CSC_060X030X039_2]  211.81 98.99 180 top
C50954  1uF_6.3V_1  [CSC_060X030X039_2]  213.28 98.96 180 top
C50955  1uF_6.3V_1  [CSC_060X030X039_2]  211.81 112.15 180 bottom
C50956  1uF_6.3V_1  [CSC_060X030X039_2]  203.53 110.65 0 top
C50957  1uF_6.3V_1  [CSC_060X030X039_2]  213.15 103.99 0 top
C50958  1uF_6.3V_1  [CSC_060X030X039_2]  209.19 98.99 0 top
C50959  1uF_6.3V_1  [CSC_060X030X039_2]  213.79 96.52 180 bottom
C50960  1uF_6.3V_1  [CSC_060X030X039_2]  213.57 112.13 180 bottom
C50961  1uF_6.3V_1  [CSC_060X030X039_2]  201.98 110.68 0 top
C50962  1uF_6.3V_1  [CSC_060X030X039_2]  203.46 99.02 0 top
C51000  4.7uF_6.3V_2  [CSC_100X050X065_2]  157.71 140.08 90 top
C51010  10uF_4V_3  [CSC_160X080X090_2]  215.29 115.62 270 top
C51011  10uF_4V_3  [CSC_160X080X090_2]  212.82 113.97 180 top
C51012  10uF_4V_3  [CSC_160X080X090_2]  200.89 119.51 180 top
C51013  10uF_4V_3  [CSC_160X080X090_2]  206.45 120.15 90 top
C51014  10uF_4V_3  [CSC_160X080X090_2]  199.34 116.34 180 top
C51015  10uF_4V_3  [CSC_160X080X090_2]  207.13 129.81 270 top
C51016  22uF_4V_3  [CSC_160X080X100_2]  210.03 130.25 90 bottom
C51017  22uF_4V_3  [CSC_160X080X100_2]  208.33 130.23 90 bottom
C51018  22uF_4V_3  [CSC_160X080X100_2]  211.81 130.25 90 bottom
C51019  22uF_4V_3  [CSC_160X080X100_2]  208.58 96.27 180 bottom
C51020  22uF_4V_3  [CSC_160X080X100_2]  215.29 130.23 90 bottom
C51021  22uF_4V_3  [CSC_160X080X100_2]  213.53 130.25 90 bottom
C51022  1uF_6.3V_1  [CSC_060X030X039_2]  211.71 118.42 180 top
C51023  1uF_6.3V_1  [CSC_060X030X039_2]  211.79 112.79 180 bottom
C51024  1uF_6.3V_1  [CSC_060X030X039_2]  213.23 126.04 180 top
C51025  1uF_6.3V_1  [CSC_060X030X039_2]  209.34 121.56 270 top
C51026  1uF_6.3V_1  [CSC_060X030X039_2]  211.79 128.43 180 bottom
C51027  1uF_6.3V_1  [CSC_060X030X039_2]  205.2 126.02 180 top
C51028  1uF_6.3V_1  [CSC_060X030X039_2]  210.26 128.43 180 bottom
C51029  1uF_6.3V_1  [CSC_060X030X039_2]  212.52 120.98 180 top
C51030  1uF_6.3V_1  [CSC_060X030X039_2]  204.09 126.02 0 top
C51031  1uF_6.3V_1  [CSC_060X030X039_2]  210.38 121.87 0 top
C51032  1uF_6.3V_1  [CSC_060X030X039_2]  201.77 114.24 0 top
C51033  1uF_6.3V_1  [CSC_060X030X039_2]  209.24 114.23 0 top
C51034  1uF_6.3V_1  [CSC_060X030X039_2]  210.28 126.04 180 top
C51035  1uF_6.3V_1  [CSC_060X030X039_2]  204.22 121.8 0 top
C51036  1uF_6.3V_1  [CSC_060X030X039_2]  204.64 117.94 270 top
C51037  1uF_6.3V_1  [CSC_060X030X039_2]  213.31 128.43 180 bottom
C51038  1uF_6.3V_1  [CSC_060X030X039_2]  208.73 126.57 180 top
C51039  1uF_6.3V_1  [CSC_060X030X039_2]  205.38 122.58 0 top
C51040  1uF_6.3V_1  [CSC_060X030X039_2]  203.6 119.18 0 top
C51041  1uF_6.3V_1  [CSC_060X030X039_2]  214.33 115.33 90 top
C51042  1uF_6.3V_1  [CSC_060X030X039_2]  208.39 121.96 180 top
C51043  1uF_6.3V_1  [CSC_060X030X039_2]  210.89 114.18 0 top
C51044  1uF_6.3V_1  [CSC_060X030X039_2]  200.3 114.74 90 top
C51045  1uF_6.3V_1  [CSC_060X030X039_2]  205.13 114.89 270 top
C51046  4.7uF_6.3V_2  [CSC_100X050X065_2]  214.89 118.42 270 top
C51047  1uF_6.3V_1  [CSC_060X030X039_2]  199.56 118.29 270 top
C51048  1uF_6.3V_1  [CSC_060X030X039_2]  214.25 122 90 top
C51049  1uF_6.3V_1  [CSC_060X030X039_2]  214.1 118.45 270 top
C51050  1uF_6.3V_1  [CSC_060X030X039_2]  200.49 121.85 180 top
C51051  1uF_6.3V_1  [CSC_060X030X039_2]  214.22 125.02 270 top
C51052  1uF_6.3V_1  [CSC_060X030X039_2]  202.39 118.63 90 top
C51053  1uF_6.3V_1  [CSC_060X030X039_2]  209.78 119.29 0 top
C51054  1uF_6.3V_1  [CSC_060X030X039_2]  211.96 119.56 180 top
C51055  1uF_6.3V_1  [CSC_060X030X039_2]  202.89 114.25 180 top
C51056  1uF_6.3V_1  [CSC_060X030X039_2]  208.39 122.6 180 top
C51057  1uF_6.3V_1  [CSC_060X030X039_2]  203.91 115.09 0 top
C51058  1uF_6.3V_1  [CSC_060X030X039_2]  206.2 116.22 90 top
C51059  1uF_6.3V_1  [CSC_060X030X039_2]  213.57 112.79 180 bottom
C51060  1uF_6.3V_1  [CSC_060X030X039_2]  211.73 126.01 180 top
C51061  1uF_6.3V_1  [CSC_060X030X039_2]  201.67 121.85 0 top
C51062  1uF_6.3V_1  [CSC_060X030X039_2]  209.12 117.99 270 top
C51110  10uF_4V_3  [CSC_160X080X090_2]  170.71 92.35 0 top
C51111  10uF_4V_3  [CSC_160X080X090_2]  165.4 87 270 top
C51112  10uF_4V_3  [CSC_160X080X090_2]  176.77 100.61 90 top
C51113  10uF_4V_3  [CSC_160X080X090_2]  175.26 85.7 270 top
C51114  10uF_4V_3  [CSC_160X080X090_2]  175.22 100.63 90 top
C51115  10uF_4V_3  [CSC_160X080X090_2]  179.07 86.57 270 top
C51116  22uF_4V_3  [CSC_160X080X100_2]  217.45 99.06 0 bottom
C51117  22uF_4V_3  [CSC_160X080X100_2]  179.09 83.56 180 bottom
C51118  22uF_4V_3  [CSC_160X080X100_2]  176.55 83.56 180 bottom
C51119  22uF_4V_3  [CSC_160X080X100_2]  167.2 83.56 0 bottom
C51120  22uF_4V_3  [CSC_160X080X100_2]  173.63 83.56 0 bottom
C51121  22uF_4V_3  [CSC_160X080X100_2]  170.15 83.56 180 bottom
C51122  1uF_6.3V_1  [CSC_060X030X039_2]  173.16 87.27 90 top
C51123  1uF_6.3V_1  [CSC_060X030X039_2]  166.95 90.1 0 top
C51124  1uF_6.3V_1  [CSC_060X030X039_2]  178.1 89.54 90 top
C51125  1uF_6.3V_1  [CSC_060X030X039_2]  173.81 88.12 180 top
C51126  1uF_6.3V_1  [CSC_060X030X039_2]  171.75 89.34 90 top
C51127  1uF_6.3V_1  [CSC_060X030X039_2]  178.12 98.65 270 top
C51128  1uF_6.3V_1  [CSC_060X030X039_2]  166.41 98 90 top
C51129  1uF_6.3V_1  [CSC_060X030X039_2]  174.44 97.59 180 top
C51130  1uF_6.3V_1  [CSC_060X030X039_2]  174.19 90.82 90 top
C51131  1uF_6.3V_1  [CSC_060X030X039_2]  166.41 91.89 90 top
C51132  1uF_6.3V_1  [CSC_060X030X039_2]  168.12 94.41 0 top
C51133  1uF_6.3V_1  [CSC_060X030X039_2]  178.12 97.17 270 top
C51134  1uF_6.3V_1  [CSC_060X030X039_2]  163.95 87.85 90 bottom
C51135  1uF_6.3V_1  [CSC_060X030X039_2]  170.15 95.38 180 top
C51136  1uF_6.3V_1  [CSC_060X030X039_2]  171.47 87.43 90 top
C51137  1uF_6.3V_1  [CSC_060X030X039_2]  166.41 96.89 270 top
C51138  1uF_6.3V_1  [CSC_060X030X039_2]  163.93 86.61 270 bottom
C51139  1uF_6.3V_1  [CSC_060X030X039_2]  171.32 98.75 270 top
C51140  1uF_6.3V_1  [CSC_060X030X039_2]  178.12 95.65 270 top
C51141  1uF_6.3V_1  [CSC_060X030X039_2]  166.44 86.74 90 top
C51142  1uF_6.3V_1  [CSC_060X030X039_2]  166.41 94.68 90 top
C51143  1uF_6.3V_1  [CSC_060X030X039_2]  166.42 95.79 270 top
C51144  1uF_6.3V_1  [CSC_060X030X039_2]  166.44 88.19 90 top
C51145  1uF_6.3V_1  [CSC_060X030X039_2]  170.5 89.35 270 top
C51146  4.7uF_6.3V_2  [CSC_100X050X065_2]  170.07 85.03 180 top
C51147  1uF_6.3V_1  [CSC_060X030X039_2]  174.03 99.74 0 top
C51148  1uF_6.3V_1  [CSC_060X030X039_2]  174.09 85.63 0 top
C51149  1uF_6.3V_1  [CSC_060X030X039_2]  170.15 85.8 180 top
C51150  1uF_6.3V_1  [CSC_060X030X039_2]  171.26 100.08 90 top
C51151  1uF_6.3V_1  [CSC_060X030X039_2]  174.49 95.25 0 top
C51152  1uF_6.3V_1  [CSC_060X030X039_2]  172.98 98.25 270 top
C51153  1uF_6.3V_1  [CSC_060X030X039_2]  170.05 90.82 180 top
C51154  1uF_6.3V_1  [CSC_060X030X039_2]  178.12 86.73 90 top
C51155  1uF_6.3V_1  [CSC_060X030X039_2]  171.29 97.64 90 top
C51156  1uF_6.3V_1  [CSC_060X030X039_2]  174.06 96.14 90 top
